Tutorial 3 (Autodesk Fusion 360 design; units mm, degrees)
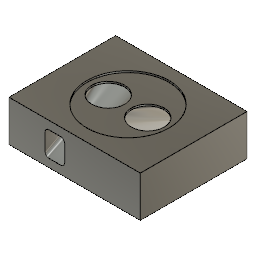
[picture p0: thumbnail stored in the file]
sketch "Sketch1" plane through (0, 0, 0) normal (0, 0, 1) x axis (1, 0, 0)
  line L1 (-80, 65) -> (80, 65)
  line L2 (-80, -65) -> (-80, 65)
  line L3 (80, -65) -> (-80, -65)
  line L4 (80, 65) -> (80, -65)
  line L5 (-80, -65) -> (80, 65)
  line L6 (80, -65) -> (-80, 65)
  point P6 (0, 0)
  point P1 (0, 0)
  point P4 (-80, -65)
  point P5 (80, -65)
  point P3 (-80, 65)
  horizontal L1
  perpendicular L1 L2
  parallel L1 L3
  parallel L2 L4
  coincident L5 P6
  coincident L6 P6
  coincident P1 P6
  dimension "d1" distance P4 P5 = 160
  dimension "d2" distance P3 P4 = 130
extrude "Extrude1" new body sketch "Sketch1" profile of L1 L2 L3 L4 along normal blind 50
sketch "Sketch2" plane through (0, 0, 50) normal (0, 0, 1) x axis (-1, 0, 0)
  line L1 (-80, -65) -> (-80, 65)
  line L2 (80, -65) -> (-80, -65)
  line L3 (80, 65) -> (80, -65)
  line L4 (-80, 65) -> (80, 65)
  circle C1 centre (0, 0) radius 50
  point P1 (0, 0)
  point P6 (0, 0)
  coincident P1 P6
  dimension "d5" diameter C1 = 100
extrude "Extrude2" cut sketch "Sketch2" profile of C1 against normal blind 2
sketch "Sketch3" plane through (0, 0, 48) normal (0, 0, 1) x axis (-1, 0, 0)
  line L1 (-80, -65) -> (-80, 65)
  line L2 (0, -95.2333) -> (0, 0)
  circle C1 centre (0, 0) radius 50
  circle C2 centre (24, 0) radius 20
  circle C3 centre (-24, 0) radius 20
  point P1 (0, 0)
  point P5 (0, 0)
  point P7 (24, 0)
  point P8 (-24, 0)
  coincident P1 P5
  parallel L1 L2
  equal C2 C3
  symmetric L2 P7 P8
  horizontal P1 P7
  dimension "d8" diameter C3 = 40
  dimension "d9" distance P7 P8 = 48
extrude "Extrude3" cut sketch "Sketch3" profile of C2 C3 against normal blind 2
sketch "Sketch4" plane through (0, -65, 0) normal (0, -1, 0) x axis (1, 0, 0)
  line L1 (80, 0) -> (-80, 0)
  line L2 (80, 50) -> (80, 0)
  line L3 (-80, 50) -> (80, 50)
  line L4 (-80, 0) -> (-80, 50)
  line L5 (-17, 40) -> (-31, 40)
  line L6 (-12, 15) -> (-12, 35)
  line L7 (-31, 10) -> (-17, 10)
  line L8 (-36, 35) -> (-36, 15)
  arc A1 centre (-31, 35) radius 5 clockwise from (-36, 35) to (-31, 40)
  arc A2 centre (-17, 35) radius 5 clockwise from (-17, 40) to (-12, 35)
  arc A3 centre (-17, 15) radius 5 clockwise from (-12, 15) to (-17, 10)
  arc A4 centre (-31, 15) radius 5 clockwise from (-31, 10) to (-36, 15)
  horizontal L5
  vertical L6
  horizontal L7
  vertical L8
  tangent L8 A1
  tangent L5 A1
  tangent L6 A2
  tangent L5 A2
  equal A1 A2
  tangent L7 A3
  tangent L6 A3
  equal A1 A3
  tangent L7 A4
  tangent L8 A4
  equal A1 A4
  dimension "d12" distance L6 L8 = 24
  dimension "d13" distance L5 L7 = 30
  dimension "d14" distance L3 L5 = 10
  dimension "d15" distance L4 L8 = 44
  dimension "d16" radius A1 = 5
loft "Loft1" sketch "Sketch4"
sketch "Sketch7" plane through (0, 65, 0) normal (0, 1, 0) x axis (-1, 0, 0)
  line L1 (80, 0) -> (-80, 0)
  line L2 (80, 50) -> (80, 0)
  line L3 (-80, 50) -> (80, 50)
  line L4 (-80, 0) -> (-80, 50)
  line L5 (-17, 40) -> (-31, 40)
  line L6 (-12, 15) -> (-12, 35)
  line L7 (-31, 10) -> (-17, 10)
  line L8 (-36, 35) -> (-36, 15)
  arc A1 centre (-31, 35) radius 5 clockwise from (-36, 35) to (-31, 40)
  arc A2 centre (-17, 35) radius 5 clockwise from (-17, 40) to (-12, 35)
  arc A3 centre (-17, 15) radius 5 clockwise from (-12, 15) to (-17, 10)
  arc A4 centre (-31, 15) radius 5 clockwise from (-31, 10) to (-36, 15)
  point P6 (-36, 40)
  point P7 (-12, 40)
  point P8 (-36, 10)
  horizontal L5
  vertical L6
  horizontal L7
  vertical L8
  coincident P6 L8
  coincident P6 L5
  tangent L8 A1
  tangent L5 A1
  coincident P7 L6
  coincident P7 L5
  tangent L6 A2
  tangent L5 A2
  equal A1 A2
  tangent L6 A3
  tangent L7 A3
  equal A1 A3
  coincident P8 L7
  coincident P8 L8
  tangent L7 A4
  tangent L8 A4
  equal A1 A4
  dimension "d18" distance P6 P7 = 24
  dimension "d19" distance P6 P8 = 30
  dimension "d20" distance L3 L5 = 10
  dimension "d21" distance L4 L8 = 44
  dimension "d22" radius A1 = 5
loft "Loft2" sketch "Sketch7"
